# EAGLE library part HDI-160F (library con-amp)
AMP connector
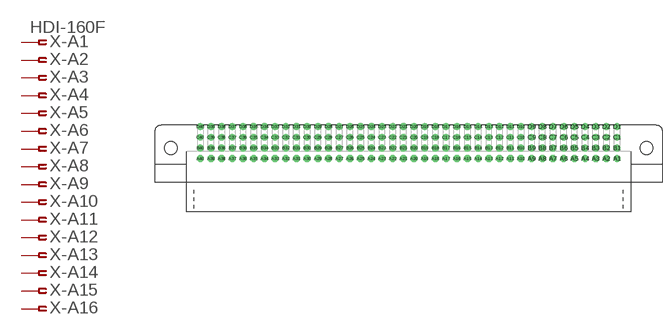
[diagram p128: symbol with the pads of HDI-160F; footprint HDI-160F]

Designator prefix X; gates -A1=PIN-FV -A2=PIN-F -A3=PIN-F -A4=PIN-F -A5=PIN-F -A6=PIN-F -A7=PIN-F -A8=PIN-F -A9=PIN-F -A10=PIN-F -A11=PIN-F -A12=PIN-F -A13=PIN-F -A14=PIN-F -A15=PIN-F -A16=PIN-F -A17=PIN-F -A18=PIN-F -A19=PIN-F -A20=PIN-F -A21=PIN-F -A22=PIN-F -A23=PIN-F -A24=PIN-F -A25=PIN-F -A26=PIN-F -A27=PIN-F -A28=PIN-F -A29=PIN-F -A30=PIN-F -A31=PIN-F -A32=PIN-F -A33=PIN-F -A34=PIN-F -A35=PIN-F -A36=PIN-F -A37=PIN-F -A38=PIN-F -A39=PIN-F -A40=PIN-F -B1=PIN-FV -B2=PIN-F -B3=PIN-F -B4=PIN-F -B5=PIN-F -B6=PIN-F -B7=PIN-F -B8=PIN-F -B9=PIN-F -B10=PIN-F -B11=PIN-F -B12=PIN-F -B13=PIN-F -B14=PIN-F -B15=PIN-F -B16=PIN-F -B17=PIN-F -B18=PIN-F -B19=PIN-F -B20=PIN-F -B21=PIN-F -B22=PIN-F -B23=PIN-F -B24=PIN-F -B25=PIN-F -B26=PIN-F -B27=PIN-F -B28=PIN-F -B29=PIN-F -B30=PIN-F -B31=PIN-F -B32=PIN-F -B33=PIN-F -B34=PIN-F -B35=PIN-F -B36=PIN-F -B37=PIN-F -B38=PIN-F -B39=PIN-F -B40=PIN-F -C1=PIN-FV -C2=PIN-F -C3=PIN-F -C4=PIN-F -C5=PIN-F -C6=PIN-F -C7=PIN-F -C8=PIN-F -C9=PIN-F -C10=PIN-F -C11=PIN-F -C12=PIN-F -C13=PIN-F -C14=PIN-F -C15=PIN-F -C16=PIN-F -C17=PIN-F -C18=PIN-F -C19=PIN-F -C20=PIN-F -C21=PIN-F -C22=PIN-F -C23=PIN-F -C24=PIN-F -C25=PIN-F -C26=PIN-F -C27=PIN-F -C28=PIN-F -C29=PIN-F -C30=PIN-F -C31=PIN-F -C32=PIN-F -C33=PIN-F -C34=PIN-F -C35=PIN-F -C36=PIN-F -C37=PIN-F -C38=PIN-F -C39=PIN-F -C40=PIN-F -D1=PIN-FV -D2=PIN-F -D3=PIN-F -D4=PIN-F -D5=PIN-F -D6=PIN-F -D7=PIN-F -D8=PIN-F -D9=PIN-F -D10=PIN-F -D11=PIN-F -D12=PIN-F -D13=PIN-F -D14=PIN-F -D15=PIN-F -D16=PIN-F -D17=PIN-F -D18=PIN-F -D19=PIN-F -D20=PIN-F -D21=PIN-F -D22=PIN-F -D23=PIN-F -D24=PIN-F -D25=PIN-F -D26=PIN-F -D27=PIN-F -D28=PIN-F -D29=PIN-F -D30=PIN-F -D31=PIN-F -D32=PIN-F -D33=PIN-F -D34=PIN-F -D35=PIN-F -D36=PIN-F -D37=PIN-F -D38=PIN-F -D39=PIN-F -D40=PIN-F

## HDI-160F (MPN: 5532434-5; OC_FARNELL: unknown; OC_NEWARK: 19R2415)  [HDI-160F]
A1  -A1:1  pas
A2  -A2:1  pas
A3  -A3:1  pas
A4  -A4:1  pas
A5  -A5:1  pas
A6  -A6:1  pas
A7  -A7:1  pas
A8  -A8:1  pas
A9  -A9:1  pas
A10  -A10:1  pas
A11  -A11:1  pas
A12  -A12:1  pas
A13  -A13:1  pas
A14  -A14:1  pas
A15  -A15:1  pas
A16  -A16:1  pas
A17  -A17:1  pas
A18  -A18:1  pas
A19  -A19:1  pas
A20  -A20:1  pas
A21  -A21:1  pas
A22  -A22:1  pas
A23  -A23:1  pas
A24  -A24:1  pas
A25  -A25:1  pas
A26  -A26:1  pas
A27  -A27:1  pas
A28  -A28:1  pas
A29  -A29:1  pas
A30  -A30:1  pas
A31  -A31:1  pas
A32  -A32:1  pas
A33  -A33:1  pas
A34  -A34:1  pas
A35  -A35:1  pas
A36  -A36:1  pas
A37  -A37:1  pas
A38  -A38:1  pas
A39  -A39:1  pas
A40  -A40:1  pas
B1  -B1:1  pas
B2  -B2:1  pas
B3  -B3:1  pas
B4  -B4:1  pas
B5  -B5:1  pas
B6  -B6:1  pas
B7  -B7:1  pas
B8  -B8:1  pas
B9  -B9:1  pas
B10  -B10:1  pas
B11  -B11:1  pas
B12  -B12:1  pas
B13  -B13:1  pas
B14  -B14:1  pas
B15  -B15:1  pas
B16  -B16:1  pas
B17  -B17:1  pas
B18  -B18:1  pas
B19  -B19:1  pas
B20  -B20:1  pas
B21  -B21:1  pas
B22  -B22:1  pas
B23  -B23:1  pas
B24  -B24:1  pas
B25  -B25:1  pas
B26  -B26:1  pas
B27  -B27:1  pas
B28  -B28:1  pas
B29  -B29:1  pas
B30  -B30:1  pas
B31  -B31:1  pas
B32  -B32:1  pas
B33  -B33:1  pas
B34  -B34:1  pas
B35  -B35:1  pas
B36  -B36:1  pas
B37  -B37:1  pas
B38  -B38:1  pas
B39  -B39:1  pas
B40  -B40:1  pas
C1  -C1:1  pas
C2  -C2:1  pas
C3  -C3:1  pas
C4  -C4:1  pas
C5  -C5:1  pas
C6  -C6:1  pas
C7  -C7:1  pas
C8  -C8:1  pas
C9  -C9:1  pas
C10  -C10:1  pas
C11  -C11:1  pas
C12  -C12:1  pas
C13  -C13:1  pas
C14  -C14:1  pas
C15  -C15:1  pas
C16  -C16:1  pas
C17  -C17:1  pas
C18  -C18:1  pas
C19  -C19:1  pas
C20  -C20:1  pas
C21  -C21:1  pas
C22  -C22:1  pas
C23  -C23:1  pas
C24  -C24:1  pas
C25  -C25:1  pas
C26  -C26:1  pas
C27  -C27:1  pas
C28  -C28:1  pas
C29  -C29:1  pas
C30  -C30:1  pas
C31  -C31:1  pas
C32  -C32:1  pas
C33  -C33:1  pas
C34  -C34:1  pas
C35  -C35:1  pas
C36  -C36:1  pas
C37  -C37:1  pas
C38  -C38:1  pas
C39  -C39:1  pas
C40  -C40:1  pas
D1  -D1:1  pas
D2  -D2:1  pas
D3  -D3:1  pas
D4  -D4:1  pas
D5  -D5:1  pas
D6  -D6:1  pas
D7  -D7:1  pas
D8  -D8:1  pas
D9  -D9:1  pas
D10  -D10:1  pas
D11  -D11:1  pas
D12  -D12:1  pas
D13  -D13:1  pas
D14  -D14:1  pas
D15  -D15:1  pas
D16  -D16:1  pas
D17  -D17:1  pas
D18  -D18:1  pas
D19  -D19:1  pas
D20  -D20:1  pas
D21  -D21:1  pas
D22  -D22:1  pas
D23  -D23:1  pas
D24  -D24:1  pas
D25  -D25:1  pas
D26  -D26:1  pas
D27  -D27:1  pas
D28  -D28:1  pas
D29  -D29:1  pas
D30  -D30:1  pas
D31  -D31:1  pas
D32  -D32:1  pas
D33  -D33:1  pas
D34  -D34:1  pas
D35  -D35:1  pas
D36  -D36:1  pas
D37  -D37:1  pas
D38  -D38:1  pas
D39  -D39:1  pas
D40  -D40:1  pas

## Footprint HDI-160F (pad centres in mm)
AMP connector
drill 1.09 octagon: A1 49.53,-2.54; A2 46.99,-2.54; A3 44.45,-2.54; A4 41.91,-2.54; A5 39.37,-2.54; A6 36.83,-2.54; A7 34.29,-2.54; A8 31.75,-2.54; A9 29.21,-2.54; A10 26.67,-2.54; A11 24.13,-2.54; A12 21.59,-2.54; A13 19.05,-2.54; A14 16.51,-2.54; A15 13.97,-2.54; A16 11.43,-2.54; A17 8.89,-2.54; A18 6.35,-2.54; A19 3.81,-2.54; A20 1.27,-2.54; A21 -1.27,-2.54; A22 -3.81,-2.54; A23 -6.35,-2.54; A24 -8.89,-2.54; A25 -11.43,-2.54; A26 -13.97,-2.54; A27 -16.51,-2.54; A28 -19.05,-2.54; A29 -21.59,-2.54; A30 -24.13,-2.54; A31 -26.67,-2.54; A32 -29.21,-2.54; A33 -31.75,-2.54; A34 -34.29,-2.54; A35 -36.83,-2.54; A36 -39.37,-2.54; A37 -41.91,-2.54; A38 -44.45,-2.54; A39 -46.99,-2.54; A40 -49.53,-2.54
drill 1.09 round: B1 49.53,0; B2 46.99,0; B3 44.45,0; B4 41.91,0; B5 39.37,0; B6 36.83,0; B7 34.29,0; B8 31.75,0; B9 29.21,0; B10 26.67,0; B11 24.13,0; B12 21.59,0; B13 19.05,0; B14 16.51,0; B15 13.97,0; B16 11.43,0; B17 8.89,0; B18 6.35,0; B19 3.81,0; B20 1.27,0; B21 -1.27,0; B22 -3.81,0; B23 -6.35,0; B24 -8.89,0; B25 -11.43,0; B26 -13.97,0; B27 -16.51,0; B28 -19.05,0; B29 -21.59,0; B30 -24.13,0; B31 -26.67,0; B32 -29.21,0; B33 -31.75,0; B34 -34.29,0; B35 -36.83,0; B36 -39.37,0; B37 -41.91,0; B38 -44.45,0; B39 -46.99,0; B40 -49.53,0; C1 49.53,2.54; C2 46.99,2.54; C3 44.45,2.54; C4 41.91,2.54; C5 39.37,2.54; C6 36.83,2.54; C7 34.29,2.54; C8 31.75,2.54; C9 29.21,2.54; C10 26.67,2.54; C11 24.13,2.54; C12 21.59,2.54; C13 19.05,2.54; C14 16.51,2.54; C15 13.97,2.54; C16 11.43,2.54; C17 8.89,2.54; C18 6.35,2.54; C19 3.81,2.54; C20 1.27,2.54; C21 -1.27,2.54; C22 -3.81,2.54; C23 -6.35,2.54; C24 -8.89,2.54; C25 -11.43,2.54; C26 -13.97,2.54; C27 -16.51,2.54; C28 -19.05,2.54; C29 -21.59,2.54; C30 -24.13,2.54; C31 -26.67,2.54; C32 -29.21,2.54; C33 -31.75,2.54; C34 -34.29,2.54; C35 -36.83,2.54; C36 -39.37,2.54; C37 -41.91,2.54; C38 -44.45,2.54; C39 -46.99,2.54; C40 -49.53,2.54; D1 49.53,5.08; D2 46.99,5.08; D3 44.45,5.08; D4 41.91,5.08; D5 39.37,5.08; D6 36.83,5.08; D7 34.29,5.08; D8 31.75,5.08; D9 29.21,5.08; D10 26.67,5.08; D11 24.13,5.08; D12 21.59,5.08; D13 19.05,5.08; D14 16.51,5.08; D15 13.97,5.08; D16 11.43,5.08; D17 8.89,5.08; D18 6.35,5.08; D19 3.81,5.08; D20 1.27,5.08; D21 -1.27,5.08; D22 -3.81,5.08; D23 -6.35,5.08; D24 -8.89,5.08; D25 -11.43,5.08; D26 -13.97,5.08; D27 -16.51,5.08; D28 -19.05,5.08; D29 -21.59,5.08; D30 -24.13,5.08; D31 -26.67,5.08; D32 -29.21,5.08; D33 -31.75,5.08; D34 -34.29,5.08; D35 -36.83,5.08; D36 -39.37,5.08; D37 -41.91,5.08; D38 -44.45,5.08; D39 -46.99,5.08; D40 -49.53,5.08
hole 3.05 at -56.51,0
hole 3.05 at 56.51,0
